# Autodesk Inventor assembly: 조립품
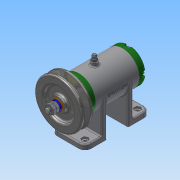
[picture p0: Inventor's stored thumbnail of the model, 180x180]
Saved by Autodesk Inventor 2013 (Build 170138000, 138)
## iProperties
Created: 2017-02
Part Number: 조립품
Document SubType Name: Assembly
Designer: Administrator
Author: Administrator
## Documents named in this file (16)
- C:\Users\Administrator\Desktop\470208V1024\조립품.iam
- C:\Users\Administrator\Desktop\470208V1024\본체.ipt
- C:\Users\Administrator\Desktop\470208V1024\V벨트풀리.ipt
- C:\Users\Administrator\Desktop\470208V1024\너트 M 8.ipt
- C:\Users\Administrator\Desktop\470208V1024\니플 M 6 x 0.75.ipt
- C:\Users\Administrator\Desktop\470208V1024\뒤커버.ipt
- C:\Users\Administrator\Desktop\470208V1024\베어링 15 x 32 x 9.ipt
- C:\Users\Administrator\Desktop\470208V1024\볼트 M 6 x 8.ipt
- C:\Users\Administrator\Desktop\470208V1024\볼트 M4 x 12.ipt
- C:\Users\Administrator\Desktop\470208V1024\스프링와셔 8.ipt
- C:\Users\Administrator\Desktop\470208V1024\앞커버.ipt
- C:\Users\Administrator\Desktop\470208V1024\오일 실 15 25 7.ipt
- C:\Users\Administrator\Desktop\470208V1024\와셔 6x11.5.ipt
- C:\Users\Administrator\Desktop\470208V1024\와셔 8x17.ipt
- C:\Users\Administrator\Desktop\470208V1024\축.ipt
- C:\Users\Administrator\Desktop\470208V1024\키 3 x 3 x 12.ipt
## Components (11 placed, 3 different names)
1. V벨트풀리:1
2. KS B 2023 6002 - 15 x 32 x 9:1
3. KS B 2023 6002 - 15 x 32 x 9:2
4. ISO 4762 M4 x 12:1
5. ISO 4762 M4 x 12:3
6. ISO 4762 M4 x 12:4
7. ISO 4762 M4 x 12:5
8. ISO 4762 M4 x 12:2
9. ISO 4762 M4 x 12:6
10. ISO 4762 M4 x 12:7
11. ISO 4762 M4 x 12:8
